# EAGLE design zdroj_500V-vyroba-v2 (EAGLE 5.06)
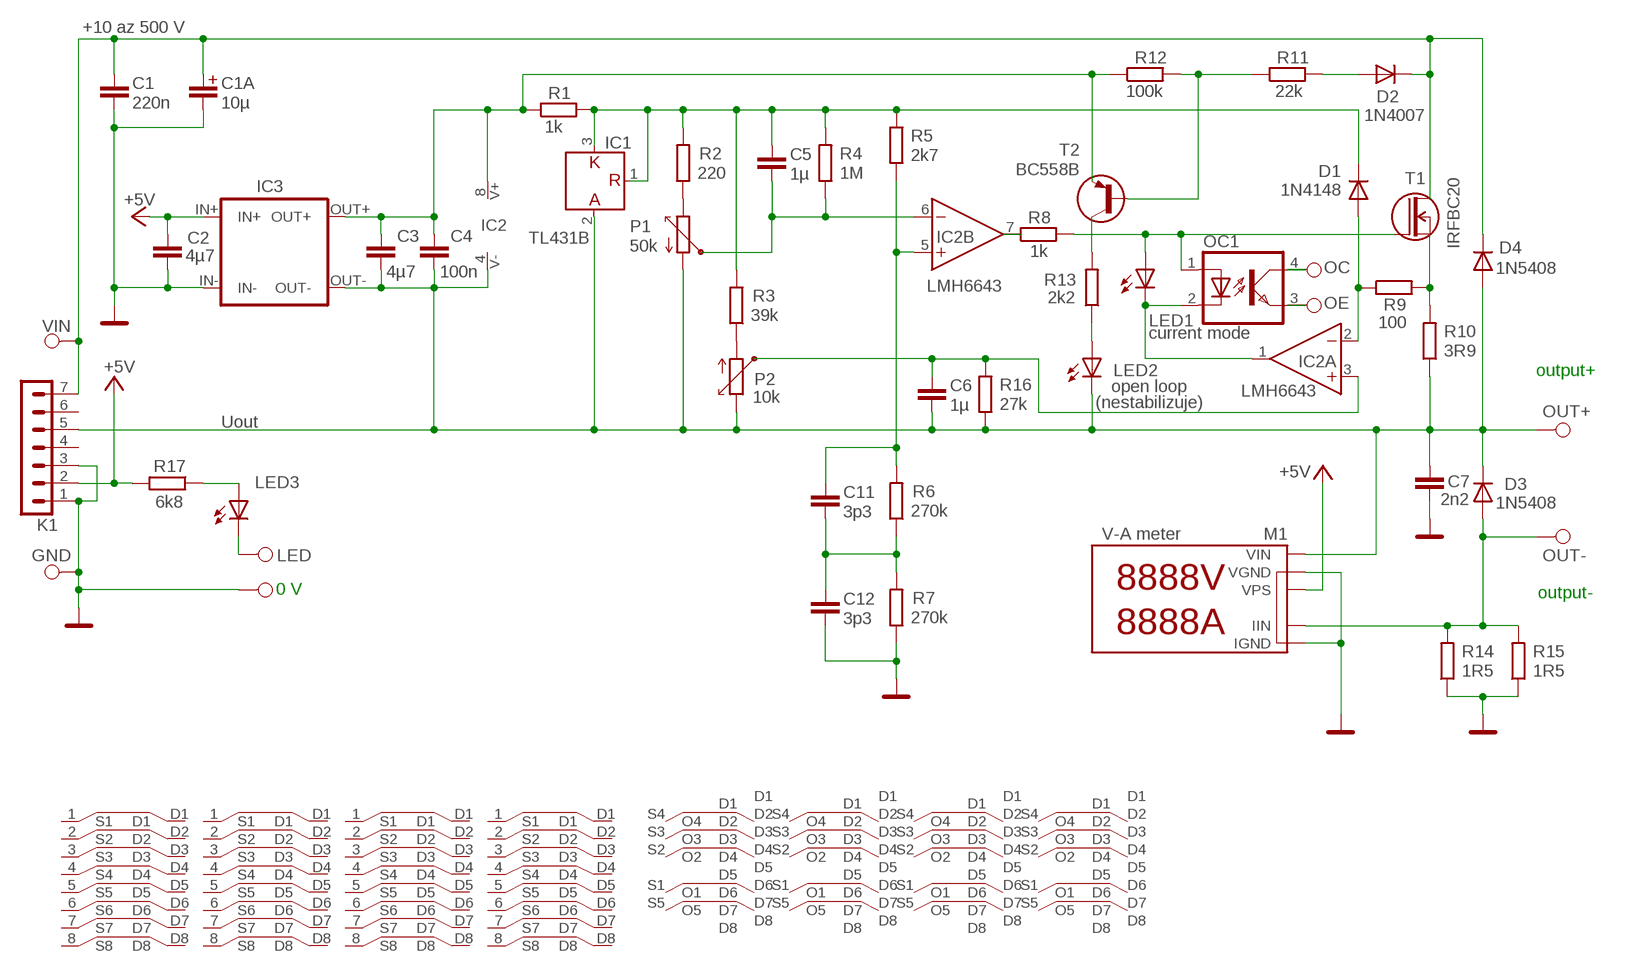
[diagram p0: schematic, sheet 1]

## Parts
.0V  PAD_1_066  [PAD_066]
C1  220n  C_CFAC_13X6_RM10  [CFAC_13X6MM_RM10]
C1A  10µ  C_ELYT_5-13  [CEL_5-13]
C2  4µ7  C_KER_RM5  [C_KER_RM5]
C3  4µ7  C_KER_RM5  [C_KER_RM5]
C4  100n  C_KER_RM5  [C_KER_RM5]
C5  1µ  C_KER_RM5  [C_KER_RM5]
C6  1µ  C_KER_RM5  [C_KER_RM5]
C7  2n2  C_KER_RM7.5  [C_KER_RM7.5]
C11  3p3  C_KER_RM5  [C_KER_RM5]
C12  3p3  C_KER_RM5  [C_KER_RM5]
D1  1N4148  DIODADO41_(1N40XX)-7MM  [DO41-7]
D2  1N4007  DIODADO41_(1N40XX)-7MM  [DO41-7]
D3  1N5408  DIODADO201_(1N54XX)-12MM  [DO201-12]
D4  1N5408  DIODADO201_(1N54XX)-15MM  [DO201-15]
GND  PAD_1_1  PAD_1_2.54/1.6MM  [PAD_1.6]
IC1  TL431B  TL431_TO92  [TO92]
IC2  LMH6643  OZ-2XN  [DIL08]
IC3  MODUL_DC/DC_SIM1  [DC-DC_SIM1]
K1  KONZ-07PSH02  [PSH02-07]
LED  PAD_1_2.54/1.4MM  [PAD_1]
LED1  LED5MM  [LED5MM]
LED2  LED5MM  [LED5MM]
LED3  LED5MM  [LED5MM]
M1  MODUL_V-A_METER-VOLT  [MODUL_V-A_METER-VOLT]
M1I  MODUL_V-A_METER-SHUNT  [MODUL_V-A_METER-SHUNT]
OC  out+  PAD_1_066  [PAD_066]
OC1  OPTOCOUPLER_4PIN_DIL4  [DIL04]
OE  out+  PAD_1_066  [PAD_066]
OUT+  out+  PAD_1_2.54/1.4MM  [PAD_1]
OUT-  PAD_1_2.54/1.4MM  [PAD_1]
P1  50k  POTENCIOMETR_PC16ML-L  [PC16ML-L]
P2  10k  POTENCIOMETR_PC16ML-L  [PC16ML-L]
R1  1k  REZISTOR_207-10  [207-10]
R2  220  REZISTOR_207-10  [207-10]
R3  39k  REZISTOR_207-10  [207-10]
R4  1M  REZISTOR_207-10  [207-10]
R5  2k7  REZISTOR_207-10  [207-10]
R6  270k  REZISTOR_207-10  [207-10]
R7  270k  REZISTOR_207-10  [207-10]
R8  1k  REZISTOR_207-10  [207-10]
R9  100  REZISTOR_207-10  [207-10]
R10  3R9  REZISTOR_309-15  [309-15]
R11  22k  REZISTOR_207-10  [207-10]
R12  100k  REZISTOR_207-10  [207-10]
R13  2k2  REZISTOR_207-10  [207-10]
R14  1R5  REZISTOR_207-10  [207-10]
R15  1R5  REZISTOR_207-10  [207-10]
R16  27k  REZISTOR_207-10  [207-10]
R17  6k8  REZISTOR_207-10  [207-10]
T1  IRFBC20  T_NFETTO220_V_HV  [TO220_V_HV]
T2  BC558B  T_PNPTO92-EBC  [TO92-EBC]
U$1  REDUKCE_SO8-DIL8  [REDUKCE_SO8-DIL8]
U$2  REDUKCE_SO8-DIL8  [REDUKCE_SO8-DIL8]
U$3  REDUKCE_SO8-DIL8  [REDUKCE_SO8-DIL8]
U$4  REDUKCE_SOT23-5-DIL8(OZ)  [REDUKCE_SOT23-5-DIL8(OZ)]
U$5  REDUKCE_SOT23-5-DIL8(OZ)  [REDUKCE_SOT23-5-DIL8(OZ)]
U$6  REDUKCE_SOT23-5-DIL8(OZ)  [REDUKCE_SOT23-5-DIL8(OZ)]
U$7  REDUKCE_SO8-DIL8  [REDUKCE_SO8-DIL8]
U$8  REDUKCE_SOT23-5-DIL8(OZ)  [REDUKCE_SOT23-5-DIL8(OZ)]
VIN  PAD_1_1  PAD_1_2.54/1.6MM  [PAD_1.6]

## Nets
+5V: C2.1 IC3.IN+ K1.2 M1.VPS R17.2
GND: .0V.1 C1.P$2 C1A.- C2.2 C7.2 C12.2 GND.1 IC3.IN- K1.1 K1.3 M1.VGND M1I.IGND R7.1 R14.1 R15.1
N$1: P1.2 R2.1
N$2: C5.2 IC2.6(B:-IN) P1.3 R4.1
N$3: IC2.7(B:OUT) R8.1
N$4: C11.2 C12.1 R6.1 R7.2
N$5: C11.1 IC2.5(B:+IN) R5.1 R6.2
N$6: LED1.A OC1.1(A) R8.2 T1.1(G)
N$7: P2.1 R3.1
N$8: R9.2 R10.2 T1.3(S)
N$9: IC2.1(A:OUT) LED1.K(C) OC1.2(C)
N$10: D1.A IC2.2(A:-IN) R9.1
N$11: LED2.A R13.1
N$12: D3.A M1I.IIN OUT-.1 R14.2 R15.2
N$13: R13.2 T2.C
N$15: C5.1 D1.K IC1.1(R) IC1.3(K) R1.2 R2.2 R3.2 R4.2 R5.2
N$16: OC1.4(COL) OC.1
N$18: C1.P$1 C1A.+ D2.K D4.K K1.7 T1.2(D) VIN.1
N$19: R11.1 R12.2 T2.B
N$20: D2.A R11.2
N$25: C6.1 IC2.3(A:+IN) P2.3 R16.2
N$26: OC1.3(EMIT) OE.1
N$30: C3.1 C4.1 IC2.8(V+) IC3.OUT+ R1.1 R12.1 T2.E
N$32: LED3.A R17.1
N$33: LED3.K(C) LED.1
N$34: C3.2 C4.2 C6.2 C7.1 D3.K D4.A IC1.2(A) IC2.4(V-) IC3.OUT- K1.5 LED2.K(C) M1.VIN OUT+.1 P1.1 P2.2 R10.1 R16.1
Unconnected: K1.4 K1.6 U$1.1(S1) U$1.2(S2) U$1.3(S3) U$1.4(S4) U$1.5(S5) U$1.6(S6) U$1.7(S7) U$1.8(S8) U$1.D1 U$1.D2 U$1.D3 U$1.D4 U$1.D5 U$1.D6 U$1.D7 U$1.D8 U$2.1(S1) U$2.2(S2) U$2.3(S3) U$2.4(S4) U$2.5(S5) U$2.6(S6) U$2.7(S7) U$2.8(S8) U$2.D1 U$2.D2 U$2.D3 U$2.D4 U$2.D5 U$2.D6 U$2.D7 U$2.D8 U$3.1(S1) U$3.2(S2) U$3.3(S3) U$3.4(S4) U$3.5(S5) U$3.6(S6) U$3.7(S7) U$3.8(S8) U$3.D1 U$3.D2 U$3.D3 U$3.D4 U$3.D5 U$3.D6 U$3.D7 U$3.D8 U$4.D1 U$4.D2 U$4.D3 U$4.D4 U$4.D5 U$4.D6 U$4.D7 U$4.D8 U$4.S1(O1) U$4.S2(O2) U$4.S3(O3) U$4.S4(O4) U$4.S5(O5) U$5.D1 U$5.D2 U$5.D3 U$5.D4 U$5.D5 U$5.D6 U$5.D7 U$5.D8 U$5.S1(O1) U$5.S2(O2) U$5.S3(O3) U$5.S4(O4) U$5.S5(O5) U$6.D1 U$6.D2 U$6.D3 U$6.D4 U$6.D5 U$6.D6 U$6.D7 U$6.D8 U$6.S1(O1) U$6.S2(O2) U$6.S3(O3) U$6.S4(O4) U$6.S5(O5) U$7.1(S1) U$7.2(S2) U$7.3(S3) U$7.4(S4) U$7.5(S5) U$7.6(S6) U$7.7(S7) U$7.8(S8) U$7.D1 U$7.D2 U$7.D3 U$7.D4 U$7.D5 U$7.D6 U$7.D7 U$7.D8 U$8.D1 U$8.D2 U$8.D3 U$8.D4 U$8.D5 U$8.D6 U$8.D7 U$8.D8 U$8.S1(O1) U$8.S2(O2) U$8.S3(O3) U$8.S4(O4) U$8.S5(O5)

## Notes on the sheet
- +10 az 500 V
- current mode
- output+
- open loop
- (nestabilizuje)
- Uout
- 0 V | output-

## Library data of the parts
.0V GND LED OC OE OUT+ OUT- VIN = #bcs7d:PAD_1: Pajeci bod - 2,54 mm prumer
C1-C7 C11 C12 = #bcs7d:C: Kondenzatory, keramicke a foliove
C1A = #bcs7d:C_ELYT: Kondenzatory, elektrolyticke
D1-D4 = #bcs7d:DIODA
IC1 = #bcs-ic1:TL431
IC2 = #bcs-ic1:OZ-2X
IC3 = #bcs_special:MODUL_DC/DC: DC-DC modul SIM1
K1 = #bcs_pinhead:KONZ-07: Konektory se zamkem - vidlice - 7pin
LED1-LED3 = #bcs7d:LED: LED
M1 = #bcs_special:MODUL_V-A_METER-VOLT
M1I = #bcs_special:MODUL_V-A_METER-SHUNT
OC1 = #bcs-ic1:OPTOCOUPLER_4PIN_: TEXAS INSTRUMENTS OPTO COUPLER
P1 P2 = #bcs7d:POTENCIOMETR
R1-R17 = #bcs7d:REZISTOR_
T1 = #bcs7d:T_NFET: N-FET
T2 = #bcs7d:T_PNP
U$1-U$3 U$7 = #bcs-ic1:REDUKCE_SO8-DIL8: Redukce SO8-DIL8
U$4-U$6 U$8 = #bcs-ic1:REDUKCE_SOT23-5-DIL8(OZ)

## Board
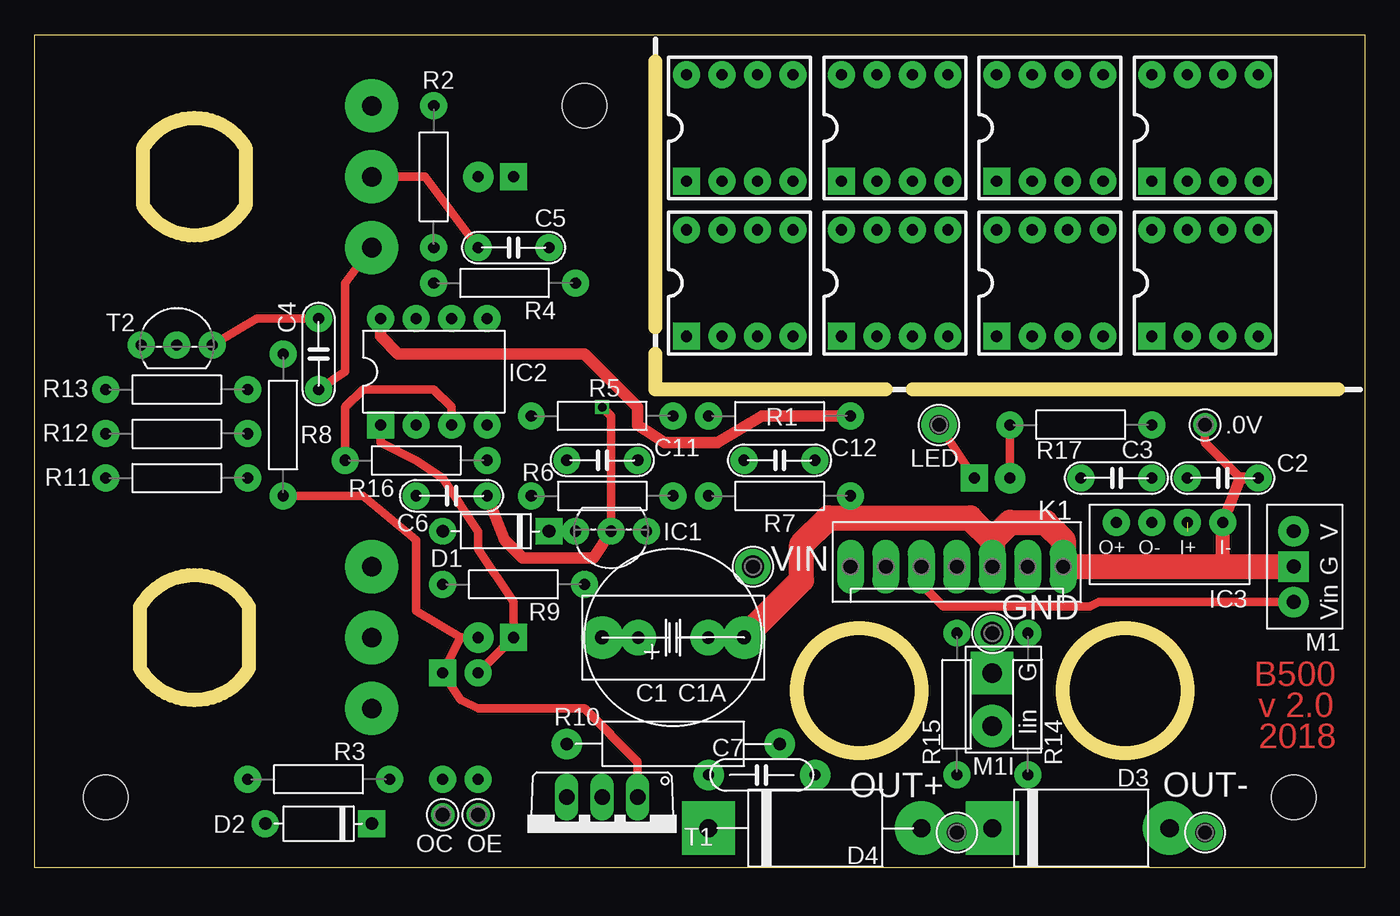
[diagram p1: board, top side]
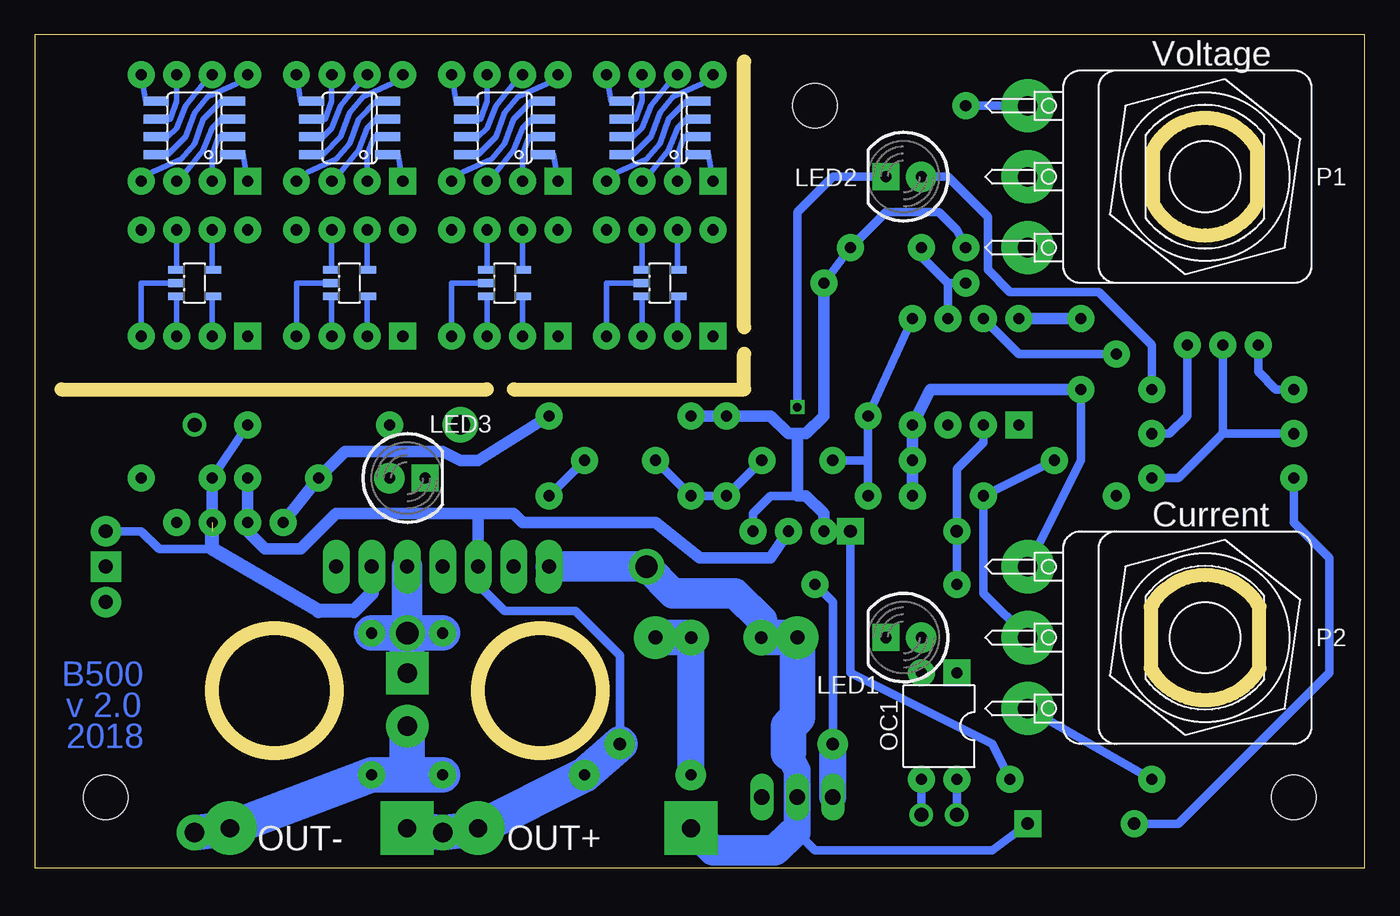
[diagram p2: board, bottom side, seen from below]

Size 95.25 x 59.69 mm. Coordinates in mm from the lower left corner, seen from the top.
Outline: 95.25,0 0,0 0,59.69 95.25,59.69 95.25,0
Copper layers (1*16): Top 0.035mm / dielectric 1.5mm / Bottom 0.035mm
Design rules "default": minimum track width 10mil, minimum drill 24mil, track to track 8mil, track to pad 8mil, pad to pad 8mil, via to via 8mil, smd to smd 8mil, copper to edge 40mil, drill to drill 8mil, minimum pad ring 10mil, minimum via ring 8mil, stop-mask expansion 4mil, vias tented up to drill 0mil, thermal gap 10mil
Holes 3.2 mm at 90.17,5.08 5.08,5.08 39.37,54.61
Milling: area 73.7,8.3 to 82.6,17.1; area 54.6,8.3 to 63.5,17.1; 12 lines

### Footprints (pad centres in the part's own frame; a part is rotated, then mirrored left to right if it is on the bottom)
PAD_066 = drill 1 pad 1.676 round: 1 0,0
CFAC_13X6MM_RM10 = drill 1 pad 3.048 round: P$1 -5.08,0; P$2 5.08,0
CEL_5-13 = drill 0.9 pad 2.54 round: + -2.5,0; - 2.5,0
C_KER_RM5 = drill 0.8 pad 1.93 round: 1 -2.54,0; 2 2.54,0
C_KER_RM7.5 = drill 0.8 pad 2.184 round: 1 -3.81,0; 2 3.81,0
DO41-7 = drill 0.9 pad 1.93 round: A 7.62,0 | drill 0.9 pad 1.93 square: K 0,0
DO201-12 = drill 1.3 pad 3.81 round: A 12.7,0 | drill 1.3 pad 3.81 square: K 0,0
DO201-15 = drill 1.3 pad 3.81 round: A 7.62,0 | drill 1.3 pad 3.81 square: K -7.62,0
PAD_1.6 = drill 1.6 pad 2.54 round: 1 0,0
TO92 = drill 0.8 pad 1.93 round: 1 -2.54,0; 2 0,0; 3 2.54,0
DIL08 = drill 0.8 pad 1.93 square: 1 -3.81,-3.81 | drill 0.8 pad 1.93 round: 2 -1.27,-3.81; 3 1.27,-3.81; 4 3.81,-3.81; 5 3.81,3.81; 6 1.27,3.81; 7 -1.27,3.81; 8 -3.81,3.81
DC-DC_SIM1 = drill 0.8 pad 1.93 round: IN+ 2.54,0; IN- 0,0; OUT+ 7.62,0; OUT- 5.08,0
PSH02-07 = drill 1 pad 1.93 long: 1 -7.62,0; 2 -5.08,0; 3 -2.54,0; 4 0,0; 5 2.54,0; 6 5.08,0; 7 7.62,0
PAD_1 = drill 1.4 pad 2.54 round: 1 0,0
LED5MM = drill 0.8 pad 2.184 round: A -1.27,0 | drill 0.8 pad 1.93 square: K 1.27,0
MODUL_V-A_METER-VOLT = drill 1 pad 2.184 square: VGND 0,0 | drill 1 pad 2.184 round: VIN 0,-2.54; VPS 0,2.54
MODUL_V-A_METER-SHUNT = drill 1.4 pad 3.048 square: IGND 0,1.27 | drill 1.4 pad 3.048 round: IIN 0,-2.54
DIL04 = drill 0.8 pad 1.93 square: 1 -1.27,-3.81 | drill 0.8 pad 1.93 round: 2 1.27,-3.81; 3 1.27,3.81; 4 -1.27,3.81
PC16ML-L = drill 1.4 pad 3.81 round: 1 -5.08,12.7; 2 5.08,12.7; 3 0,12.7
207-10 = drill 0.8 pad 1.93 round: 1 -5.08,0; 2 5.08,0
309-15 = drill 0.9 pad 2.184 round: 1 -7.62,0; 2 7.62,0
TO220_V_HV = drill 1.1 pad 1.676 long: 1 -2.54,-2.54; 2 0,-2.54; 3 2.54,-2.54
TO92-EBC = drill 0.8 pad 1.93 round: B 0,-1.27; C -2.54,-1.27; E 2.54,-1.27
REDUKCE_SO8-DIL8 = smd 1.778 x 0.635 bottom: 1 -2.731,-1.905; 2 -2.731,-0.635; 3 -2.731,0.635; 4 -2.731,1.905; 5 2.731,1.905; 6 2.731,0.635; 7 2.731,-0.635; 8 2.731,-1.905 | drill 0.8 pad 1.93 square: D1 -3.81,-3.81 | drill 0.8 pad 1.93 round: D2 -1.27,-3.81; D3 1.27,-3.81; D4 3.81,-3.81; D5 3.81,3.81; D6 1.27,3.81; D7 -1.27,3.81; D8 -3.81,3.81
REDUKCE_SOT23-5-DIL8(OZ) = drill 0.8 pad 1.93 square: D1 -3.81,-3.81 | drill 0.8 pad 1.93 round: D2 -1.27,-3.81; D3 1.27,-3.81; D4 3.81,-3.81; D5 3.81,3.81; D6 1.27,3.81; D7 -1.27,3.81; D8 -3.81,3.81 | smd 1.2 x 0.55 bottom: S1 1.3,0.95; S2 1.3,0; S3 1.3,-0.95; S4 -1.3,-0.95; S5 -1.3,0.95

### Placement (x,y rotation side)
.0V  83.82,31.75 0 top
C1  45.72,16.51 0 top
C1A  45.72,16.51 0 top
C2  85.09,27.94 0 top
C3  77.47,27.94 0 top
C4  20.32,36.83 270 top
C5  34.29,44.45 180 top
C6  29.84,26.67 0 top
C7  52.07,6.67 180 top
C11  40.64,29.21 0 top
C12  53.34,29.21 0 top
D1  36.83,24.13 180 top
D2  24.13,3.17 180 top
D3  68.58,2.86 0 top
D4  55.88,2.86 0 top
GND  68.58,16.83 0 top
IC1  41.27,24.13 180 top
IC2  28.57,35.56 0 top
IC3  85.09,24.77 180 top
K1  66.04,21.59 180 top
LED  64.77,31.75 0 top
LED1  33.02,16.51 180 bottom
LED2  33.02,49.53 180 bottom
LED3  68.58,27.94 0 bottom
M1  90.17,21.59 0 top
M1I  68.58,12.7 0 top
OC  29.21,3.81 0 top
OC1  30.48,10.16 180 bottom
OE  31.75,3.81 0 top
OUT+  66.04,2.54 0 top
OUT-  83.82,2.54 0 top
P1  11.43,49.53 90 bottom
P2  11.43,16.51 90 bottom
R1  53.34,32.38 180 top
R2  28.57,49.53 270 top
R3  20.32,6.35 0 top
R4  33.66,41.91 0 top
R5  40.64,32.38 0 top
R6  40.64,26.67 180 top
R7  53.34,26.67 180 top
R8  17.78,31.75 270 top
R9  34.29,20.32 0 top
R10  45.72,8.89 180 top
R11  10.16,27.94 180 top
R12  10.16,31.11 180 top
R13  10.16,34.29 180 top
R14  71.12,11.75 270 top
R15  66.04,11.75 270 top
R16  27.3,29.21 180 top
R17  74.93,31.75 0 top
T1  40.64,2.54 180 top
T2  10.16,38.73 0 top
U$1  50.48,53.02 0 top
U$2  61.59,53.02 0 top
U$3  72.71,53.02 0 top
U$4  50.48,41.91 0 top
U$5  61.59,41.91 0 top
U$6  72.71,41.91 0 top
U$7  83.82,53.02 0 top
U$8  83.82,41.91 0 top
VIN  51.44,21.59 0 top

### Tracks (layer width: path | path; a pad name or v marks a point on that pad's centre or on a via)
+5V  (1 unrouted)
  Bottom 0.61: 82.55,22.86 86.36,22.86 87.63,24.13 M1.VPS | C2.1 R17.2
  Bottom 0.813: 82.55,24.13 C2.1
  Bottom 1.016: K1.2 71.12,19.68 72.39,18.41 74.93,18.41 82.55,22.86 IC3.IN+
GND
  Top 0.61: 58.42,25.08 R7.1 | .0V.1 83.82,30.48 86.36,27.94
  Top 0.813: IC3.IN- 86.36,27.94 C2.2
  Top 1.016: 85.09,21.59 IC3.IN-
  Top 1.778: C1.P$2 54.93,20.64 54.93,23.18 56.83,25.08 58.42,25.08 66.99,25.08 68.58,23.5 | 68.58,23.5 K1.3 | 68.58,23.5 69.85,24.77 72.39,24.77 73.66,23.5 K1.1 85.09,21.59 M1.VGND
  Bottom 0.61: R7.1 C12.2
  Bottom 1.778: 48.26,16.51 C1A.-
  Bottom 1.93: C7.2 48.26,16.51
  Bottom 2.184: K1.3 GND.1
  Bottom 2.54: C1A.- C1.P$2 | GND.1 R14.1 | GND.1 R15.1 | GND.1 M1I.IGND
N$1
  Bottom 0.61: R2.1 P1.2
N$2
  Top 0.61: P1.3 27.94,49.53 C5.2
  Bottom 0.61: C5.2 31.75,43.81 29.84,41.91 | IC2.6 29.84,41.91 | R4.1 29.84,41.91
N$3
  Bottom 0.61: IC2.7 24.77,36.83 R8.1
N$4
  Bottom 0.61: C12.1 R7.2 R6.1 C11.2
N$5
  Bottom 0.61: R6.2 35.56,29.21 | 35.56,29.21 R5.1 IC2.5 | 35.56,29.21 C11.1
N$6
  Top 0.61: R8.2 23.5,26.67 27.3,23.5 27.3,18.41 30.48,16.51 | T1.1 43.18,7.62 39.37,11.43 31.75,11.43 30.48,12.06 OC1.1 30.48,16.51 | 30.48,16.51 LED1.A
N$7
  Bottom 0.61: R3.1 P2.1
N$8
  Bottom 0.61: R9.2 38.1,19.05 R10.2
  Bottom 1.93: T1.3 R10.2
N$9
  Top 0.61: IC2.1 24.77,30.48 27.3,29.21 29.21,27.94 31.75,24.13 31.75,22.86 34.29,19.05 LED1.K OC1.2
N$10
  Bottom 0.61: R9.1 D1.A 29.21,28.57 27.3,30.48 IC2.2
N$11
  Bottom 0.61: R13.1 15.24,37.47 19.05,41.27 25.4,41.27 26.99,42.86 26.99,46.67 29.84,49.53 LED2.A
N$12
  Bottom 2.54: OUT-.1 D3.A R14.2 68.58,6.67 | 68.58,6.67 R15.2 | 68.58,6.67 M1I.IIN
N$13
  Bottom 0.61: T2.C 7.62,35.56 6.35,34.29 R13.2
N$15
  Bottom 0.61: R3.2 26.67,8.89 36.83,13.97 D1.K IC1.3 | IC1.1 43.81,25.4 42.55,26.67 40.64,26.67 | R4.2 C5.1 34.29,46.99 30.48,46.99 29.21,45.72 R2.2
  Bottom 0.813: R1.2 R5.2 42.55,32.38 41.27,31.11 40.64,31.11 | 40.64,31.11 40.64,26.67 40.01,26.67 38.73,25.4 IC1.3 | 40.64,31.11 40.01,31.11 38.73,32.38 R4.2
N$16
  Bottom 0.61: OC1.4 OC.1
N$18
  Bottom 0.61: D2.K 26.67,1.27 39.37,1.27 40.64,2.54
  Bottom 1.93: 57.78,21.59 K1.7 | 41.27,8.26 40.64,6.99 T1.2 40.64,2.54 40.96,2.54
  Bottom 2.184: C1A.+ 43.18,17.78 45.09,19.68 49.53,19.68 VIN.1 57.78,21.59 | 40.96,2.54 42.23,1.27 46.67,1.27 D4.K
  Bottom 2.54: C1A.+ C1.P$1 40.64,10.79 41.27,10.16 41.27,8.26
N$19
  Bottom 0.61: R11.1 13.34,27.94 10.16,31.11 | 10.16,31.11 T2.B | 10.16,31.11 R12.2
N$20
  Bottom 0.61: D2.A 13.34,3.17 2.54,13.97 2.54,22.23 5.08,24.77 R11.2
N$25
  Top 0.61: IC2.3 29.84,33.02 28.57,34.29 23.5,34.29 22.23,33.02 R16.2
  Bottom 0.61: R16.2 C6.1 27.3,19.68 P2.3
N$26
  Bottom 0.61: OC1.3 OE.1
N$30
  Top 0.61: C4.1 15.88,39.37 T2.E
  Top 0.813: R1.1 52.07,32.38 48.9,30.48 45.09,30.48 43.18,31.75 43.18,33.02 39.37,36.83 26.04,36.83 24.77,38.1 IC2.8
  Bottom 0.61: R12.1 13.97,31.11 12.7,32.38 T2.E
  Bottom 0.813: C4.1 IC2.8 | R1.1 63.5,29.21 64.77,29.21 66.04,29.84 73.03,29.84 C3.1 IC3.OUT+
N$32
  Top 0.61: R17.1 LED3.A
N$33
  Top 0.61: LED.1 LED3.K
N$34  (via drill 0.6)
  Top 0.61: P1.1 22.23,41.91 22.23,35.56 C4.2 | K1.5 63.5,20.32 65.09,18.73 75.56,18.73 76.2,19.05 M1.VIN | IC1.2 41.27,32.38 v40.64,33.02
  Top 0.813: C6.2 33.66,23.5 34.92,22.23 40.01,22.23 IC1.2
  Bottom 0.61: C4.2 20.32,29.21 P2.2 | K1.5 63.5,20.32 61.59,18.41 56.52,18.41 53.34,15.24 R10.1 | LED2.K 38.1,49.53 40.64,46.99 v40.64,33.02
  Bottom 0.813: C4.2 31.11,34.29 IC2.4 R16.1 C6.2 | 63.5,25.4 60.96,25.4 60.33,24.77 50.8,24.77 47.62,22.23 42.55,22.23 IC1.2 | 63.5,25.4 K1.5 | 63.5,25.4 73.66,25.4 76.2,22.86 78.74,22.86 80.01,24.13 IC3.OUT- C3.2
  Bottom 2.54: D3.K OUT+.1 D4.A C7.1 R10.1

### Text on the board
Top: B500 | v 2.0 | 2018
Bottom: B500 | v 2.0 | 2018
bPlace: Voltage | Current | OUT- | OUT+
